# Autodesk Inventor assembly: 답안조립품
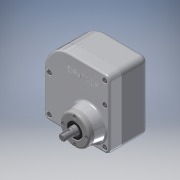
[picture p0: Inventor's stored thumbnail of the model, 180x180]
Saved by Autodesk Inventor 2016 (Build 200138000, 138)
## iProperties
Created: 2015-11
Part Number: 답안조립품
Document SubType Name: Assembly
Designer: Administrator
Author: Administrator
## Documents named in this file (13)
- C:\Users\Administrator\Downloads\Inventor2급\2급\공용부품_20151104_2\답안조립품.iam
- C:\Users\Administrator\Downloads\Inventor2급\2급\공용부품_20151104_2\1-본체.ipt
- C:\Users\Administrator\Downloads\Inventor2급\2급\공용부품_20151104_2\로드 축.ipt
- C:\Users\Administrator\Downloads\Inventor2급\2급\공용부품_20151104_2\로드.ipt
- C:\Users\Administrator\Downloads\Inventor2급\2급\공용부품_20151104_2\베어링 6001.ipt
- C:\Users\Administrator\Downloads\Inventor2급\2급\공용부품_20151104_2\베어링 6002.ipt
- C:\Users\Administrator\Downloads\Inventor2급\2급\공용부품_20151104_2\앞커버.ipt
- C:\Users\Administrator\Downloads\Inventor2급\2급\공용부품_20151104_2\오일실 15 x 25.ipt
- C:\Users\Administrator\Downloads\Inventor2급\2급\공용부품_20151104_2\오일실 12 x 22.ipt
- C:\Users\Administrator\Downloads\Inventor2급\2급\공용부품_20151104_2\축 커버.ipt
- C:\Users\Administrator\Downloads\Inventor2급\2급\공용부품_20151104_2\편심 축.ipt
- C:\Users\Administrator\Downloads\Inventor2급\2급\공용부품_20151104_2\M3 x 0.5.ipt
- C:\Users\Administrator\Downloads\Inventor2급\2급\공용부품_20151104_2\M4 x 0.7.ipt
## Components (10 placed, 3 different names)
1. 1-본체:1 — Mate:1, Mate:2, Mate:4, Mate:5, Mate:7, Mate:8, Mate:9, Mate:10, Mate:11, Mate:20, Mate:22, Mate:27, Insert:2, Insert:3, Insert:4, Insert:5, Insert:6, Drive
2. M4 x 0.7:1 — Insert:2
3. M4 x 0.7:2 — Insert:3
4. M4 x 0.7:3 — Insert:4
5. M4 x 0.7:4 — Insert:5
6. M4 x 0.7:5 — Insert:6
7. M3 x 0.5:1 — Insert:1
8. M3 x 0.5:2
9. M3 x 0.5:3
10. M3 x 0.5:4
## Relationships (19: Mate 12, Insert 6, Angle 1)
- Mate:1: 1-본체:1
- Mate:2: 1-본체:1
- Mate:4: 1-본체:1
- Mate:5: 1-본체:1
- Mate:7: 1-본체:1
- Mate:8: 1-본체:1
- Mate:9: 1-본체:1
- Mate:10: 1-본체:1
- Mate:11: 1-본체:1
- Mate:20: 1-본체:1
- Mate:22: 1-본체:1
- Mate:27: 1-본체:1
- Insert:1: M3 x 0.5:1
- Insert:2: 1-본체:1 ↔ M4 x 0.7:1
- Insert:3: 1-본체:1 ↔ M4 x 0.7:2
- Insert:4: 1-본체:1 ↔ M4 x 0.7:3
- Insert:5: 1-본체:1 ↔ M4 x 0.7:4
- Insert:6: 1-본체:1 ↔ M4 x 0.7:5
- Drive [Angle]: 1-본체:1
